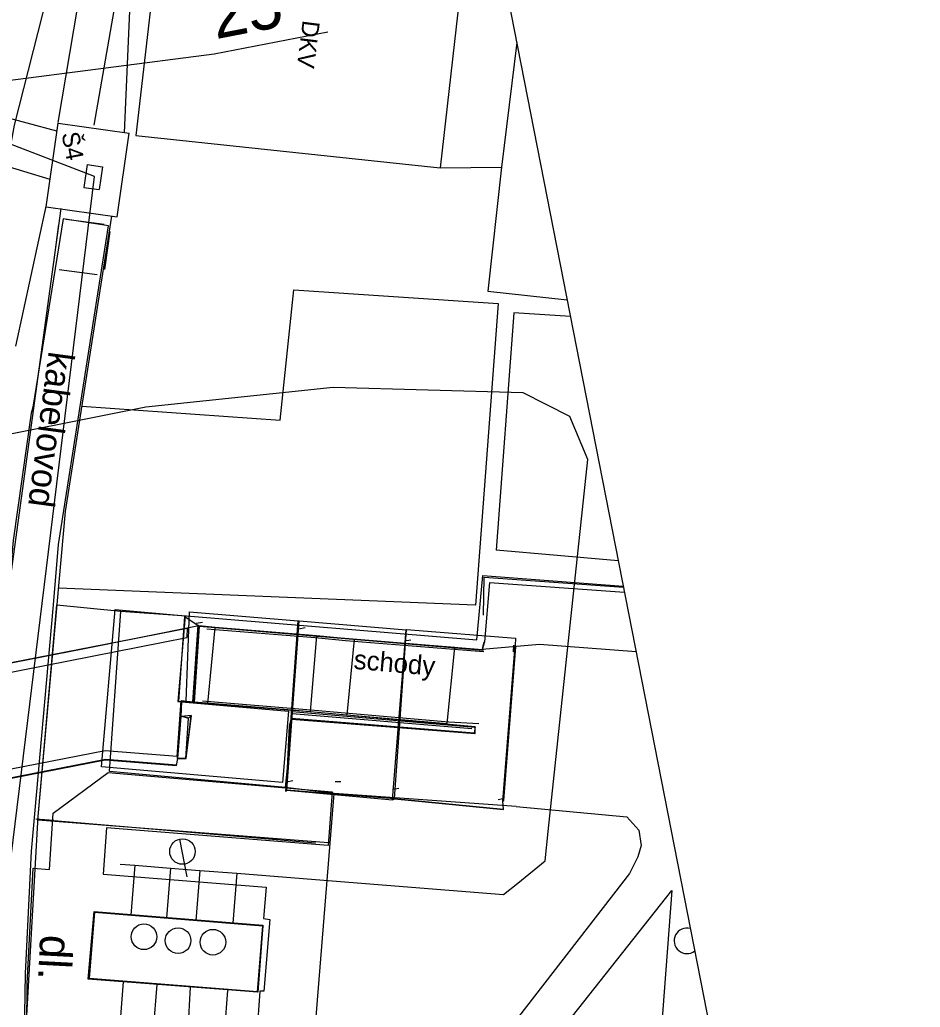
# Model space of a CAD drawing. Extents: x -545736 to -544888, y -1122892 to -1119128.
# Drawn here: x -545098.74 to -545063.59, y -1121893.1 to -1121854.55 of the extents above; entities that cross this region are included whole.
import ezdxf

# ---------------------------------------------------------------- set-up
doc = ezdxf.new("R2010")
doc.units = 0
for name, color, linetype in [('so180602', 7, 'Continuous'), ('Vrstva 1', 7, 'Continuous'), ('Vrstva 10', 7, 'Continuous'), ('Vrstva 12', 7, 'Continuous'), ('Vrstva 13', 7, 'Continuous'), ('Vrstva 16', 7, 'Continuous'), ('Vrstva 16_plochy', 7, 'Continuous'), ('Vrstva 17', 7, 'Continuous'), ('Vrstva 23', 7, 'Continuous'), ('Vrstva 26', 7, 'Continuous'), ('Vrstva 28 - zabzar', 7, 'Continuous'), ('Vrstva 34', 7, 'Continuous'), ('Vrstva 35', 7, 'Continuous'), ('Vrstva 36', 7, 'Continuous'), ('Vrstva 43', 7, 'Continuous'), ('Vrstva 44', 7, 'Continuous'), ('Vrstva 49', 7, 'Continuous'), ('Vrstva 51', 7, 'Continuous'), ('Vrstva 61', 7, 'Continuous'), ('Vrstva 63', 7, 'Continuous')]:
    doc.layers.add(name, color=color, linetype=linetype)

msp = doc.modelspace()

# ---------------------------------------------------------------- linework, layer by layer
at = {"layer": 'Vrstva 1'}
msp.add_lwpolyline([(-545102.113, -1121882.835), (-545100.504, -1121867.161), (-545098.949, -1121858.665), (-545095.447, -1121844.904), (-545093.58, -1121839.064)], dxfattribs=at)
at = {"layer": 'Vrstva 10'}
msp.add_line((-545169.988, -1121392.291), (-544887.573, -1122835.274), dxfattribs=at)
at = {"layer": 'Vrstva 12'}
for p, q in [((-545091.744, -1121878.229), (-545080.661, -1121879.164)), ((-545091.742, -1121878.223), (-545080.697, -1121879.143)), ((-545080.961, -1121882.161), (-545088.12, -1121881.506)), ((-545088.135, -1121881.821), (-545081.007, -1121882.393)), ((-545088.133, -1121881.857), (-545080.965, -1121882.414)), ((-545088.11, -1121881.552), (-545080.968, -1121882.166))]:
    msp.add_line(p, q, dxfattribs=at)
for points in [[(-545080.697, -1121879.143), (-545080.661, -1121879.164), (-545080.668, -1121879.046), (-545080.612, -1121878.854), (-545080.607, -1121878.843)], [(-545088.135, -1121881.821), (-545088.133, -1121881.857), (-545088.11, -1121881.552), (-545088.12, -1121881.506)], [(-545081.007, -1121882.393), (-545080.965, -1121882.414), (-545080.968, -1121882.166), (-545080.961, -1121882.161)]]:
    msp.add_lwpolyline(points, close=True, dxfattribs=at)
at = {"layer": 'Vrstva 13'}
for p, q in [((-545080.404, -1121876.52), (-545080.607, -1121878.843)), ((-545080.404, -1121876.52), (-545075.143, -1121876.894)), ((-545086.434, -1121884.293), (-545086.206, -1121884.284)), ((-545095.823, -1121889.394), (-545096.035, -1121891.974)), ((-545089.253, -1121889.92), (-545095.823, -1121889.394)), ((-545095.823, -1121889.394), (-545095.823, -1121889.394)), ((-545089.467, -1121892.504), (-545089.253, -1121889.92)), ((-545089.253, -1121889.92), (-545089.253, -1121889.92)), ((-545096.035, -1121891.974), (-545089.467, -1121892.504)), ((-545096.035, -1121891.974), (-545096.035, -1121891.974)), ((-545089.467, -1121892.504), (-545089.467, -1121892.504))]:
    msp.add_line(p, q, dxfattribs=at)
msp.add_lwpolyline([(-545095.823, -1121889.394), (-545089.253, -1121889.92), (-545089.467, -1121892.504), (-545096.035, -1121891.974)], close=True, dxfattribs=at)
at = {"layer": 'Vrstva 16'}
for p, q in [((-545098.898, -1121867.298), (-545097.703, -1121861.777)), ((-545097.301, -1121877.394), (-545094.801, -1121877.641))]:
    msp.add_line(p, q, dxfattribs=at)
msp.add_lwpolyline([(-545097.238, -1121858.566), (-545095.875, -1121850.476), (-545094.302, -1121850.614), (-545094.671, -1121858.975)], dxfattribs=at)
at = {"layer": 'Vrstva 16_plochy'}
for points in [[(-545098.215, -1121887.678), (-545097.587, -1121887.719), (-545097.442, -1121885.53), (-545095.293, -1121883.941), (-545086.545, -1121884.699), (-545086.706, -1121886.794), (-545095.356, -1121886.1), (-545095.488, -1121887.903), (-545089.123, -1121888.41), (-545089.236, -1121889.64), (-545088.977, -1121889.679), (-545089.217, -1121892.479), (-545089.376, -1121892.473), (-545089.487, -1121894.138), (-545089.236, -1121894.164), (-545089.743, -1121900.67), (-545089.989, -1121900.65), (-545090.111, -1121901.889), (-545098.356, -1121901.24), (-545098.5, -1121897.205), (-545098.451, -1121892.174), (-545098.215, -1121887.678)], [(-545096.079, -1121892.002), (-545095.844, -1121889.363), (-545089.25, -1121889.899), (-545089.455, -1121892.511), (-545096.079, -1121892.002)]]:
    msp.add_lwpolyline(points, dxfattribs=at)
at = {"layer": 'Vrstva 17'}
for p, q in [((-545082.339, -1121860.337), (-545079.943, -1121860.312)), ((-545081.102, -1121882.234), (-545088.113, -1121881.643))]:
    msp.add_line(p, q, dxfattribs=at)
for points in [[(-545092.231, -1121877.825), (-545080.899, -1121878.763), (-545080.673, -1121876.248), (-545075.188, -1121876.663)], [(-545080.646, -1121877.793), (-545080.615, -1121876.31), (-545075.182, -1121876.698)], [(-545091.435, -1121878.33), (-545087.209, -1121878.665), (-545086.027, -1121878.784), (-545081.795, -1121879.126), (-545080.63, -1121879.218)], [(-545080.83, -1121882.033), (-545081.993, -1121881.971), (-545086.194, -1121881.612), (-545087.381, -1121881.506), (-545091.606, -1121881.151)], [(-545082.003, -1122004.082), (-545087.068, -1121968.072), (-545086.898, -1121965.319), (-545092.427, -1121958.663), (-545086.474, -1121884.755), (-545088.37, -1121884.526)]]:
    msp.add_lwpolyline(points, dxfattribs=at)
at = {"layer": 'Vrstva 23'}
for p, q in [((-545081.382, -1121851.971), (-545082.339, -1121860.337)), ((-545092.251, -1121881.156), (-545092.121, -1121877.664)), ((-545088.357, -1121884.678), (-545087.87, -1121878.022)), ((-545088.318, -1121884.623), (-545087.84, -1121878.02)), ((-545143.668, -1121888.303), (-545092.208, -1121878.305)), ((-545092.219, -1121878.316), (-545120.835, -1121883.939)), ((-545092.208, -1121878.305), (-545092.216, -1121878.665)), ((-545091.396, -1121881.243), (-545091.113, -1121878.276)), ((-545084.198, -1121885), (-545083.663, -1121878.365)), ((-545084.122, -1121884.962), (-545083.653, -1121878.36)), ((-545120.759, -1121884.295), (-545092.216, -1121878.665)), ((-545087.157, -1121878.604), (-545087.41, -1121881.564)), ((-545085.695, -1121878.747), (-545085.975, -1121881.693)), ((-545079.892, -1121885.063), (-545079.404, -1121878.978)), ((-545079.85, -1121885.037), (-545079.374, -1121879.031)), ((-545092.603, -1121883.309), (-545092.438, -1121881.139)), ((-545091.991, -1121881.19), (-545092.438, -1121881.139)), ((-545092.473, -1121881.727), (-545092.159, -1121881.812)), ((-545079.866, -1121885.379), (-545079.892, -1121885.063))]:
    msp.add_line(p, q, dxfattribs=at)
for points in [[(-545093.242, -1121850.62), (-545094.216, -1121859.075), (-545082.339, -1121860.337)], [(-545079.341, -1121855.445), (-545079.943, -1121860.312)], [(-545079.943, -1121860.312), (-545080.468, -1121865.148), (-545077.375, -1121865.493)], [(-545088.37, -1121884.526), (-545095.236, -1121883.898), (-545094.801, -1121877.641), (-545092.231, -1121877.825)], [(-545088.12, -1121881.506), (-545091.936, -1121881.193), (-545092.53, -1121881.171), (-545092.303, -1121877.848), (-545091.744, -1121878.229), (-545091.936, -1121881.193)], [(-545092.121, -1121877.664), (-545087.87, -1121878.022), (-545087.84, -1121878.02), (-545083.663, -1121878.365), (-545083.653, -1121878.36), (-545079.397, -1121878.691), (-545079.404, -1121878.978), (-545079.374, -1121879.031)], [(-545091.758, -1121878.218), (-545096.276, -1121879.121), (-545120.851, -1121883.909)], [(-545092.418, -1121881.159), (-545091.396, -1121881.243), (-545087.41, -1121881.564), (-545085.975, -1121881.693), (-545082.055, -1121882.031), (-545081.764, -1121879.055), (-545085.695, -1121878.747), (-545087.157, -1121878.604), (-545091.113, -1121878.276), (-545091.758, -1121878.218)], [(-545091.937, -1121881.189), (-545091.991, -1121881.19), (-545091.785, -1121878.191), (-545091.744, -1121878.229)], [(-545091.936, -1121881.193), (-545091.937, -1121881.189), (-545091.742, -1121878.223), (-545091.744, -1121878.229)], [(-545091.758, -1121878.219), (-545091.758, -1121878.218), (-545091.785, -1121878.191)], [(-545119.878, -1121888.237), (-545095.406, -1121883.444), (-545092.628, -1121883.665), (-545092.578, -1121883.394), (-545092.252, -1121883.397), (-545092.056, -1121881.717), (-545092.44, -1121881.752), (-545092.418, -1121881.159), (-545091.396, -1121881.243)], [(-545092.438, -1121881.139), (-545092.418, -1121881.159), (-545092.418, -1121881.159)], [(-545092.251, -1121881.156), (-545088.125, -1121881.503)], [(-545092.159, -1121881.812), (-545092.056, -1121881.717), (-545092.258, -1121883.397), (-545092.601, -1121883.396)], [(-545092.252, -1121883.397), (-545092.258, -1121883.397), (-545092.159, -1121881.812), (-545092.473, -1121881.727), (-545092.601, -1121883.396)], [(-545088.37, -1121884.526), (-545088.288, -1121883.775), (-545088.211, -1121882.114), (-545088.135, -1121881.821)], [(-545088.288, -1121883.775), (-545088.282, -1121883.779), (-545088.146, -1121882.145), (-545088.211, -1121882.114)], [(-545092.603, -1121883.309), (-545095.411, -1121883.091), (-545118.037, -1121887.503)], [(-545092.617, -1121883.654), (-545095.398, -1121883.427), (-545117.967, -1121887.839)], [(-545088.357, -1121884.678), (-545088.318, -1121884.623), (-545084.198, -1121885), (-545084.122, -1121884.962), (-545079.866, -1121885.379)], [(-545079.866, -1121885.379), (-545084.122, -1121884.962), (-545088.318, -1121884.623)], [(-545079.892, -1121885.063), (-545079.85, -1121885.037)]]:
    msp.add_lwpolyline(points, dxfattribs=at)
for points in [[(-545088.491, -1121884.325), (-545095.558, -1121883.712), (-545095.026, -1121877.582), (-545092.287, -1121877.82), (-545092.578, -1121881.171), (-545088.25, -1121881.546)], [(-545092.44, -1121881.752), (-545092.473, -1121881.727), (-545092.601, -1121883.396), (-545092.578, -1121883.394)]]:
    msp.add_lwpolyline(points, close=True, dxfattribs=at)
at = {"layer": 'Vrstva 26'}
msp.add_lwpolyline([(-545097.437, -1122052.623), (-545072.287, -1122039.894), (-545085.621, -1122009.744), (-545089.841, -1121964.946), (-545095.239, -1121958.274), (-545095.745, -1121940.272), (-545098.424, -1121935.947), (-545099.088, -1121910.293), (-545099.581, -1121891.247), (-545095.82, -1121860.673), (-545104.239, -1121857.434), (-545113.591, -1121811.167), (-545113.924, -1121803.223), (-545124.359, -1121753.762), (-545132.104, -1121728.782), (-545141.308, -1121704.806), (-545150.282, -1121669.65), (-545151.919, -1121656.143), (-545151.404, -1121636.531), (-545180.167, -1121637.447), (-545212.798, -1121581.796), (-545235.977, -1121514.184), (-545242.54, -1121484.599), (-545257.211, -1121409.362)], dxfattribs=at)
at = {"layer": 'Vrstva 28 - zabzar'}
msp.add_lwpolyline([(-545095.84, -1121858.67), (-545094.42, -1121850.52), (-545092.44, -1121842.5), (-545093.47, -1121842.25), (-545095.68, -1121841.73), (-545096.79, -1121841.54), (-545097.03, -1121841.97)], dxfattribs=at)
at = {"layer": 'Vrstva 34'}
for p, q in [((-545097.416, -1121864.034), (-545097.214, -1121862.548)), ((-545096.932, -1121862.334), (-545095.446, -1121862.536)), ((-545095.232, -1121862.818), (-545095.434, -1121864.304)), ((-545095.716, -1121864.518), (-545097.202, -1121864.316))]:
    msp.add_line(p, q, dxfattribs=at)
at = {"layer": 'Vrstva 35'}
msp.add_lwpolyline([(-545094.766, -1121939.919), (-545097.515, -1121935.57), (-545098.514, -1121899.276), (-545098.598, -1121896.563), (-545098.524, -1121891.782), (-545098.28, -1121887.009), (-545097.43, -1121877.391), (-545097.227, -1121875.04), (-545095.278, -1121862.596), (-545097.055, -1121862.323), (-545098.236, -1121869.684), (-545098.293, -1121869.911), (-545099.003, -1121874.881), (-545099.214, -1121877.242), (-545100.072, -1121886.841), (-545100.302, -1121891.691), (-545100.433, -1121896.532), (-545100.323, -1121899.371), (-545099.288, -1121936.136), (-545096.606, -1121940.329)], dxfattribs=at)
at = {"layer": 'Vrstva 36'}
for p, q in [((-545091.853, -1121878.115), (-545091.608, -1121878.067)), ((-545087.848, -1121878.333), (-545087.603, -1121878.285)), ((-545083.722, -1121878.802), (-545083.477, -1121878.754)), ((-545079.473, -1121879.222), (-545079.453, -1121878.973)), ((-545088.329, -1121884.297), (-545088.084, -1121884.249)), ((-545084.189, -1121884.595), (-545083.944, -1121884.547)), ((-545080.074, -1121884.99), (-545079.829, -1121884.942))]:
    msp.add_line(p, q, dxfattribs=at)
at = {"layer": 'Vrstva 43'}
msp.add_line((-545092.203, -1121888.007), (-545092.489, -1121886.536), dxfattribs=at)
for centre, radius in [((-545092.394, -1121887.025), 0.498), ((-545093.895, -1121890.352), 0.5), ((-545092.563, -1121890.502), 0.5), ((-545091.205, -1121890.563), 0.5)]:
    msp.add_circle(centre, radius, dxfattribs=at)
msp.add_arc((-545072.7, -1121890.509), 0.5, 75.3415, 306.8059, dxfattribs=at)
at = {"layer": 'Vrstva 44'}
for p, q in [((-545094.254, -1121887.557), (-545094.408, -1121889.507)), ((-545092.865, -1121887.668), (-545093.02, -1121889.618)), ((-545091.72, -1121887.758), (-545091.875, -1121889.71)), ((-545090.268, -1121887.873), (-545090.422, -1121889.826)), ((-545094.841, -1121893.966), (-545094.692, -1121892.115)), ((-545093.529, -1121894.058), (-545093.383, -1121892.216)), ((-545092.186, -1121894.167), (-545092.085, -1121892.315)), ((-545090.758, -1121894.286), (-545090.618, -1121892.451))]:
    msp.add_line(p, q, dxfattribs=at)
msp.add_lwpolyline([(-545094.826, -1121887.512), (-545094.254, -1121887.557), (-545092.865, -1121887.668), (-545091.72, -1121887.758), (-545090.268, -1121887.873), (-545086.549, -1121888.168), (-545079.866, -1121888.698), (-545079.307, -1121888.256), (-545078.235, -1121887.388), (-545078.119, -1121886.246), (-545076.573, -1121871.721), (-545077.268, -1121870.044), (-545079.088, -1121869.124), (-545086.504, -1121868.907), (-545093.818, -1121869.676), (-545108.699, -1121872.648), (-545109.324, -1121872.781), (-545110.052, -1121872.845), (-545138.969, -1121878.416), (-545139.513, -1121878.622), (-545139.779, -1121877.836), (-545147.175, -1121839.811)], dxfattribs=at)
at = {"layer": 'Vrstva 49'}
for p, q in [((-545097.295, -1121858.905), (-545102.311, -1121857.563)), ((-545097.708, -1121861.853), (-545097.244, -1121858.586)), ((-545097.244, -1121858.586), (-545094.472, -1121858.979)), ((-545094.936, -1121862.247), (-545094.472, -1121858.979)), ((-545097.557, -1121860.788), (-545101.938, -1121859.477)), ((-545096.111, -1121860.211), (-545096.238, -1121861.102)), ((-545096.111, -1121860.211), (-545095.517, -1121860.295)), ((-545095.517, -1121860.295), (-545095.644, -1121861.186)), ((-545096.238, -1121861.102), (-545095.644, -1121861.186)), ((-545097.708, -1121861.853), (-545094.936, -1121862.247))]:
    msp.add_line(p, q, dxfattribs=at)
for points in [[(-545097.144, -1121861.928), (-545099.25, -1121877.31), (-545100.173, -1121886.859)], [(-545095.159, -1121862.217), (-545096.968, -1121873.754)], [(-545096.968, -1121873.754), (-545098.032, -1121885.658)], [(-545086.693, -1121886.686), (-545098.04, -1121885.803), (-545097.301, -1121877.394)], [(-545085.497, -1122001.114), (-545088.91, -1121965.171), (-545094.295, -1121957.978), (-545094.881, -1121939.771), (-545097.424, -1121935.631), (-545098.653, -1121896.621), (-545098.031, -1121885.652)]]:
    msp.add_lwpolyline(points, dxfattribs=at)
at = {"layer": 'Vrstva 51'}
for p, q in [((-545079.458, -1121866.001), (-545080.152, -1121875.256)), ((-545075.381, -1121875.677), (-545080.152, -1121875.256)), ((-545080.955, -1121877.403), (-545097.235, -1121876.739)), ((-545078.454, -1121878.942), (-545080.697, -1121879.143)), ((-545079.362, -1121885.268), (-545086.474, -1121884.755)), ((-545097.415, -1121885.812), (-545087.206, -1121886.686))]:
    msp.add_line(p, q, dxfattribs=at)
for points in [[(-545096.322, -1121869.634), (-545088.575, -1121870.191), (-545088.052, -1121865.098), (-545080.074, -1121865.629), (-545080.955, -1121877.403)], [(-545077.249, -1121866.135), (-545079.458, -1121866.001)], [(-545074.687, -1121879.228), (-545078.454, -1121878.942)], [(-545079.362, -1121885.268), (-545075.053, -1121885.671), (-545074.578, -1121886.186), (-545074.491, -1121886.791), (-545074.615, -1121887.234), (-545074.937, -1121887.875), (-545082.675, -1121897.858), (-545082.851, -1121900)], [(-545097.415, -1121885.812), (-545098.116, -1121885.763)], [(-545080.741, -1121900), (-545080.597, -1121897.802), (-545073.289, -1121888.539), (-545074.009, -1121898), (-545070.977, -1121898.182)]]:
    msp.add_lwpolyline(points, dxfattribs=at)
at = {"layer": 'Vrstva 63'}
for p, q in [((-545086.715, -1121855.033), (-545091.159, -1121855.897)), ((-545091.159, -1121855.897), (-545111.881, -1121858.592))]:
    msp.add_line(p, q, dxfattribs=at)

# ---------------------------------------------------------------- texts
at = {"layer": 'so180602'}
msp.add_text('25', height=1.875, rotation=10.9955, dxfattribs=at).set_placement((-545091.098, -1121855.317))
at = {"layer": 'Vrstva 16'}
msp.add_text('kabelovod', height=1, rotation=262.3673, dxfattribs=at).set_placement((-545097.609, -1121867.47))
at = {"layer": 'Vrstva 16_plochy'}
msp.add_text('dl.', height=1.25, rotation=266.9952, dxfattribs=at).set_placement((-545097.941, -1121890.256))
at = {"layer": 'Vrstva 23'}
for s, height, rotation, p in [('DKV', 0.6744, 262.8567, (-545087.697, -1121854.556)), ('schody', 0.75, 355.0719, (-545085.728, -1121879.89))]:
    msp.add_text(s, height=height, rotation=rotation, dxfattribs=at).set_placement(p)
at = {"layer": 'Vrstva 61'}
msp.add_text('Š4', height=0.6806, rotation=281.0281, dxfattribs=at).set_placement((-545097.116, -1121859))

doc.saveas('drawing.dxf')
